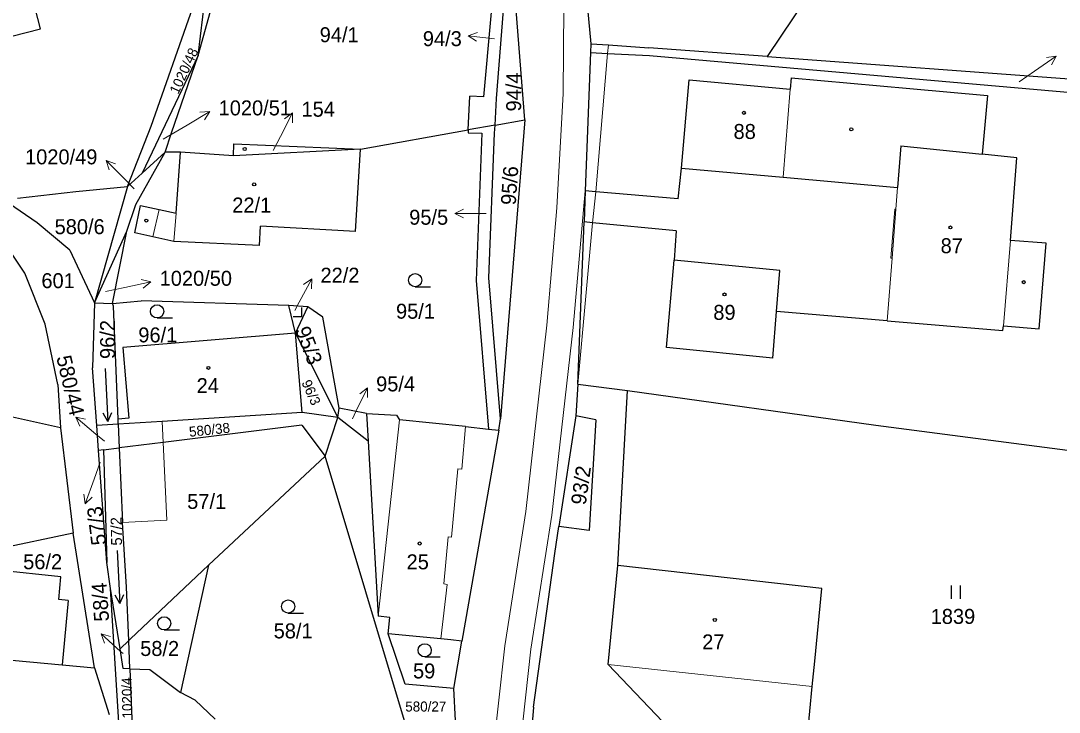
# Model space of a CAD drawing. Extents: x -601131 to -597152, y -1058536 to -1055911.
# Drawn here: x -599472.1 to -599354.1, y -1057055.1 to -1056976.5 of the extents above; entities that cross this region are included whole.
import ezdxf
from ezdxf.enums import TextEntityAlignment as Align

# ---------------------------------------------------------------- set-up
doc = ezdxf.new("R2010")
doc.units = 0
doc.header["$LTSCALE"] = 0.68
for name, color, linetype, lineweight in [('1', 7, 'Continuous', 25), ('13', 7, 'Continuous', 13), ('3', 7, 'Continuous', 25), ('4', 7, 'Continuous', 13), ('5', 7, 'Continuous', 25), ('7', 7, 'Continuous', 13)]:
    doc.layers.add(name, color=color, linetype=linetype, lineweight=lineweight)
doc.layers.add('2', color=7, linetype='Continuous')

msp = doc.modelspace()

# ---------------------------------------------------------------- linework, layer by layer
at = {"layer": '1'}
for p, q in [((-599409.1, -1056959.5), (-599407.35, -1056979.16)), ((-599469.83, -1056977.46), (-599473.08, -1056964.77)), ((-599418.06, -1056985.36), (-599416.53, -1056966.46)), ((-599414.84, -1056987.77), (-599416.53, -1056966.46)), ((-599451.94, -1056980.47), (-599450.86, -1056971.71)), ((-599381.53, -1056971.98), (-599387.3, -1056980.59)), ((-599457.28, -1056988.51), (-599452.54, -1056975.02)), ((-599451.94, -1056980.47), (-599450.36, -1056974.77)), ((-599482.74, -1056980.66), (-599469.83, -1056977.46)), ((-599407.35, -1056979.16), (-599407.36, -1056980.13)), ((-599407.35, -1056979.16), (-599405.34, -1056979.25)), ((-599405.34, -1056979.25), (-599400.73, -1056979.59)), ((-599387.3, -1056980.59), (-599400.73, -1056979.59)), ((-599451.94, -1056980.47), (-599458.28, -1056993.82)), ((-599454.95, -1056989.27), (-599451.94, -1056980.47)), ((-599407.36, -1056980.13), (-599407.96, -1056995.84)), ((-599407.36, -1056980.13), (-599405.42, -1056980.23)), ((-599405.42, -1056980.23), (-599400.68, -1056980.47)), ((-599400.68, -1056980.47), (-599338.49, -1056985.92)), ((-599387.3, -1056980.59), (-599338.23, -1056984.23)), ((-599397.05, -1056993.26), (-599396.16, -1056983.24)), ((-599396.16, -1056983.24), (-599384.69, -1056984.29)), ((-599384.57, -1056983), (-599384.69, -1056984.29)), ((-599384.57, -1056983), (-599371.09, -1056984.22)), ((-599371.09, -1056984.22), (-599362.27, -1056985.01)), ((-599421.26, -1056988.92), (-599421.08, -1056985.09)), ((-599418.21, -1056988.37), (-599418.06, -1056985.36)), ((-599362.27, -1056985.01), (-599362.87, -1056991.68)), ((-599418.21, -1056988.37), (-599414.84, -1056987.77)), ((-599414.84, -1056987.77), (-599417.59, -1057021.75)), ((-599459.98, -1056995.37), (-599457.28, -1056988.51)), ((-599455.67, -1056991.45), (-599454.95, -1056989.27)), ((-599433.51, -1056991.1), (-599421.26, -1056988.92)), ((-599421.26, -1056988.92), (-599421.28, -1056989.24)), ((-599421.28, -1056989.24), (-599419.7, -1056989.31)), ((-599418.21, -1056988.37), (-599421.26, -1056988.92)), ((-599419.7, -1056989.31), (-599420.34, -1057006.01)), ((-599418.91, -1057005.71), (-599418.26, -1056989.29)), ((-599418.26, -1056989.29), (-599418.21, -1056988.37)), ((-599447.93, -1056991.85), (-599447.87, -1056990.49)), ((-599447.87, -1056990.49), (-599433.51, -1056991.1)), ((-599459.02, -1056997.4), (-599455.67, -1056991.45)), ((-599458.28, -1056993.82), (-599455.67, -1056991.45)), ((-599453.94, -1056991.44), (-599455.67, -1056991.45)), ((-599454.45, -1056998.37), (-599453.94, -1056991.44)), ((-599447.93, -1056991.85), (-599453.94, -1056991.44)), ((-599433.51, -1056991.1), (-599447.93, -1056991.85)), ((-599434.07, -1057000.46), (-599433.51, -1056991.1)), ((-599372.12, -1056990.74), (-599372.49, -1056995.45)), ((-599372.12, -1056990.74), (-599362.87, -1056991.68)), ((-599358.94, -1056992.08), (-599362.87, -1056991.68)), ((-599359.68, -1057001.47), (-599358.94, -1056992.08)), ((-599470.21, -1056999.49), (-599478.7, -1056993.76)), ((-599459.98, -1056995.37), (-599458.28, -1056993.82)), ((-599397.4, -1056996.74), (-599397.05, -1056993.26)), ((-599397.05, -1056993.26), (-599385.47, -1056994.29)), ((-599385.47, -1056994.29), (-599372.49, -1056995.45)), ((-599472.45, -1056996.68), (-599465.82, -1056995.91)), ((-599465.82, -1056995.91), (-599459.98, -1056995.37)), ((-599459.98, -1056995.37), (-599463.72, -1057008.55)), ((-599407.96, -1056995.84), (-599408.09, -1056999.38)), ((-599406.78, -1056995.94), (-599407.96, -1056995.84)), ((-599397.4, -1056996.74), (-599406.78, -1056995.94)), ((-599460.03, -1057000.43), (-599459.02, -1056997.4)), ((-599459.12, -1057000.61), (-599458.49, -1056997.5)), ((-599458.49, -1056997.5), (-599456.38, -1056997.96)), ((-599456.38, -1056997.96), (-599454.45, -1056998.37)), ((-599466.52, -1057002.58), (-599470.21, -1056999.49)), ((-599444.97, -1057002.05), (-599444.85, -1056999.86)), ((-599434.07, -1057000.46), (-599444.85, -1056999.86)), ((-599408.79, -1057017.81), (-599408.09, -1056999.38)), ((-599407.13, -1056999.47), (-599408.09, -1056999.38)), ((-599397.65, -1057000.39), (-599407.13, -1056999.47)), ((-599463.72, -1057008.55), (-599460.03, -1057000.43)), ((-599461.67, -1057008.63), (-599460.03, -1057000.43)), ((-599457.07, -1057001.07), (-599459.12, -1057000.61)), ((-599454.69, -1057001.61), (-599457.07, -1057001.07)), ((-599397.65, -1057000.39), (-599397.85, -1057003.72)), ((-599444.97, -1057002.05), (-599454.69, -1057001.61)), ((-599355.61, -1057001.8), (-599359.68, -1057001.47)), ((-599356.39, -1057011.51), (-599355.61, -1057001.8)), ((-599471.61, -1057005.21), (-599473.53, -1057002.36)), ((-599466.52, -1057002.58), (-599463.72, -1057008.55)), ((-599398.74, -1057013.65), (-599397.85, -1057003.72)), ((-599385.87, -1057004.88), (-599397.85, -1057003.72)), ((-599469.32, -1057010.99), (-599471.61, -1057005.21)), ((-599417.59, -1057021.75), (-599418.91, -1057005.71)), ((-599386.24, -1057009.56), (-599385.87, -1057004.88)), ((-599420.34, -1057006.01), (-599418.94, -1057022.91)), ((-599463.72, -1057008.55), (-599463.92, -1057015.93)), ((-599463.72, -1057008.55), (-599461.67, -1057008.63)), ((-599461.67, -1057008.63), (-599458.42, -1057008.35)), ((-599461.55, -1057008.94), (-599461.67, -1057008.63)), ((-599461.04, -1057021.77), (-599461.55, -1057008.94)), ((-599441.62, -1057008.88), (-599458.42, -1057008.35)), ((-599439.46, -1057009), (-599441.62, -1057008.88)), ((-599440.89, -1057012), (-599441.62, -1057008.88)), ((-599440.89, -1057012), (-599439.46, -1057009)), ((-599437.78, -1057010.19), (-599439.46, -1057009)), ((-599435.93, -1057020.54), (-599437.78, -1057010.19)), ((-599386.66, -1057014.83), (-599386.24, -1057009.56)), ((-599373.69, -1057010.61), (-599386.24, -1057009.56)), ((-599467.86, -1057017.84), (-599469.32, -1057010.99)), ((-599373.69, -1057010.61), (-599360.53, -1057011.71)), ((-599360.53, -1057011.71), (-599360.46, -1057011.18)), ((-599360.46, -1057011.18), (-599356.39, -1057011.51)), ((-599440.89, -1057012), (-599460.49, -1057013.64)), ((-599440.89, -1057012), (-599436.08, -1057021.6)), ((-599440.13, -1057021), (-599440.89, -1057012)), ((-599460.49, -1057013.64), (-599459.82, -1057021.67)), ((-599386.66, -1057014.83), (-599398.74, -1057013.65)), ((-599463.44, -1057022.51), (-599463.92, -1057015.93)), ((-599467.56, -1057022.76), (-599489.04, -1057018.02)), ((-599467.86, -1057017.84), (-599467.56, -1057022.76)), ((-599408.79, -1057017.81), (-599409.03, -1057021.4)), ((-599408.79, -1057017.81), (-599403.17, -1057018.53)), ((-599404.27, -1057038.38), (-599403.17, -1057018.53)), ((-599403.17, -1057018.53), (-599374.96, -1057022.46)), ((-599440.13, -1057021), (-599456.04, -1057022.03)), ((-599436.08, -1057021.6), (-599440.13, -1057021)), ((-599436.08, -1057021.6), (-599435.93, -1057020.54)), ((-599432.8, -1057021.13), (-599435.93, -1057020.54)), ((-599432.8, -1057021.13), (-599432.62, -1057024.26)), ((-599432.8, -1057021.13), (-599429.39, -1057021.33)), ((-599461.01, -1057022.35), (-599463.44, -1057022.51)), ((-599459.82, -1057021.67), (-599461.04, -1057021.77)), ((-599461.01, -1057022.35), (-599461.04, -1057021.77)), ((-599456.04, -1057022.03), (-599461.01, -1057022.35)), ((-599461.01, -1057022.35), (-599460.9, -1057025.03)), ((-599437.5, -1057025.97), (-599436.08, -1057021.6)), ((-599432.62, -1057024.26), (-599436.08, -1057021.6)), ((-599429.39, -1057021.33), (-599429.05, -1057021.83)), ((-599421.58, -1057022.62), (-599429.05, -1057021.83)), ((-599417.77, -1057023.04), (-599417.59, -1057021.75)), ((-599409.03, -1057021.4), (-599410.96, -1057033.98)), ((-599406.78, -1057021.84), (-599409.03, -1057021.4)), ((-599406.78, -1057021.84), (-599407.53, -1057034.4)), ((-599467.56, -1057022.76), (-599466.14, -1057034.71)), ((-599463.24, -1057025.32), (-599463.44, -1057022.51)), ((-599440.17, -1057022.45), (-599455.92, -1057024.41)), ((-599440.17, -1057022.45), (-599437.5, -1057025.97)), ((-599417.77, -1057023.04), (-599421.97, -1057047)), ((-599421.58, -1057022.62), (-599418.94, -1057022.91)), ((-599418.94, -1057022.91), (-599417.77, -1057023.04)), ((-599374.96, -1057022.46), (-599345.57, -1057026.31)), ((-599455.92, -1057024.41), (-599460.9, -1057025.03)), ((-599432.62, -1057024.26), (-599431.47, -1057044.16)), ((-599462.69, -1057025.25), (-599463.24, -1057025.32)), ((-599462.31, -1057038.06), (-599463.24, -1057025.32)), ((-599462.69, -1057025.25), (-599460.9, -1057025.03)), ((-599462.69, -1057025.25), (-599462.31, -1057038.06)), ((-599460.9, -1057025.03), (-599460.52, -1057033.5)), ((-599450.76, -1057038.35), (-599437.5, -1057025.97)), ((-599428.27, -1057056.8), (-599437.5, -1057025.97)), ((-599460.07, -1057040.85), (-599460.52, -1057033.5)), ((-599411.41, -1057037.02), (-599410.96, -1057033.98)), ((-599407.53, -1057034.4), (-599410.96, -1057033.98)), ((-599466.14, -1057034.71), (-599476.85, -1057036.98)), ((-599463.71, -1057050), (-599466.14, -1057034.71)), ((-599413.85, -1057054.49), (-599411.41, -1057037.02)), ((-599467.53, -1057039.67), (-599480.14, -1057038.37)), ((-599461.88, -1057041.02), (-599462.31, -1057038.06)), ((-599459.62, -1057046.73), (-599450.76, -1057038.35)), ((-599450.76, -1057038.35), (-599453.93, -1057052.81)), ((-599405.37, -1057049.65), (-599404.27, -1057038.38)), ((-599381.08, -1057041), (-599404.27, -1057038.38)), ((-599467.75, -1057042.26), (-599467.53, -1057039.67)), ((-599460.81, -1057047.86), (-599461.88, -1057041.02)), ((-599460.91, -1057056.82), (-599461.88, -1057041.02)), ((-599459.82, -1057046.92), (-599460.07, -1057040.85)), ((-599381.87, -1057049.25), (-599381.08, -1057041)), ((-599466.69, -1057042.35), (-599467.75, -1057042.26)), ((-599466.69, -1057042.35), (-599467.37, -1057049.67)), ((-599430.18, -1057044.28), (-599431.47, -1057044.16)), ((-599430.36, -1057046.16), (-599430.18, -1057044.28)), ((-599459.82, -1057046.92), (-599460.81, -1057047.86)), ((-599459.82, -1057046.92), (-599459.62, -1057046.73)), ((-599459.69, -1057050.12), (-599459.82, -1057046.92)), ((-599428.44, -1057051.87), (-599430.36, -1057046.16)), ((-599424.38, -1057046.72), (-599430.36, -1057046.16)), ((-599423.25, -1057046.85), (-599424.38, -1057046.72)), ((-599421.97, -1057047), (-599423.25, -1057046.85)), ((-599422.91, -1057052.37), (-599421.97, -1057047)), ((-599488.12, -1057047.79), (-599467.37, -1057049.67)), ((-599460.46, -1057050.1), (-599460.81, -1057047.86)), ((-599382.18, -1057052.14), (-599381.87, -1057049.25)), ((-599467.37, -1057049.67), (-599463.71, -1057050)), ((-599463.71, -1057050), (-599462.05, -1057055.3)), ((-599459.69, -1057050.12), (-599460.46, -1057050.1)), ((-599459.69, -1057050.12), (-599459.42, -1057056.74)), ((-599459.69, -1057050.12), (-599457.43, -1057050.19)), ((-599457.43, -1057050.19), (-599453.93, -1057052.81)), ((-599393.36, -1057062.2), (-599405.37, -1057049.65)), ((-599452.28, -1057053.7), (-599453.93, -1057052.81)), ((-599422.91, -1057052.37), (-599428.44, -1057051.87)), ((-599422.72, -1057056), (-599422.91, -1057052.37)), ((-599383.28, -1057063.21), (-599382.18, -1057052.14)), ((-599450.01, -1057055.83), (-599452.28, -1057053.7)), ((-599413.85, -1057054.49), (-599415.07, -1057069.81))]:
    msp.add_line(p, q, dxfattribs=at)
msp.add_lwpolyline([(-599417.86, -1056966.74), (-599419.51, -1056985.16), (-599421.08, -1056985.09)], dxfattribs=at)
at = {"layer": '13'}
for points in [[(-599416.28, -1057067.22), (-599414.13, -1057047.91), (-599411.76, -1057032.68), (-599409.33, -1057011.38), (-599407.96, -1056995.84), (-599407.36, -1056980.13), (-599407.35, -1056979.16), (-599409.1, -1056959.5), (-599412.79, -1056937.66), (-599414.89, -1056928.62), (-599418.98, -1056914.8), (-599422.34, -1056903.17), (-599429.56, -1056878.4), (-599431.63, -1056868.93), (-599432.99, -1056860.71)], [(-599435.97, -1056861.08), (-599434.58, -1056869.5), (-599432.48, -1056879.1), (-599425.21, -1056904.03), (-599421.86, -1056915.62), (-599416.39, -1056935.17), (-599414.31, -1056943.54), (-599413.29, -1056949.55), (-599410.84, -1056967.85), (-599410.4, -1056975), (-599410.48, -1056984.78), (-599411.21, -1056997.76), (-599412.32, -1057011.09), (-599414.73, -1057032.27), (-599417.11, -1057047.5), (-599419.27, -1057067.05)]]:
    msp.add_lwpolyline(points, dxfattribs=at)
at = {"layer": '3'}
for p, q in [((-599427.293, -1057006.74), (-599425.543, -1057006.74)), ((-599456.603, -1057010.28), (-599454.853, -1057010.28)), ((-599462.191, -1057022.023), (-599462.743, -1057021.074)), ((-599366.361, -1057042.18), (-599366.361, -1057040.68)), ((-599365.36, -1057042.18), (-599365.36, -1057040.68)), ((-599460.821, -1057042.693), (-599461.373, -1057041.744)), ((-599441.703, -1057043.8), (-599439.953, -1057043.8)), ((-599455.803, -1057045.71), (-599454.053, -1057045.71)), ((-599426.203, -1057048.77), (-599424.453, -1057048.77))]:
    msp.add_line(p, q, dxfattribs=at)
for points in [[(-599441.151, -1057010.11), (-599440.15, -1057010.11), (-599440.15, -1057009.11)], [(-599462.505, -1057016.032), (-599462.191, -1057022.023), (-599461.741, -1057021.021)], [(-599461.135, -1057036.702), (-599460.821, -1057042.693), (-599460.371, -1057041.691)]]:
    msp.add_lwpolyline(points, dxfattribs=at)
for centre in [(-599427.2929, -1057005.9898), (-599456.6029, -1057009.5298), (-599441.7029, -1057043.0498), (-599455.8029, -1057044.9598), (-599426.2029, -1057048.0198)]:
    msp.add_circle(centre, 0.75, dxfattribs=at)
at = {"layer": '4'}
for p, q in [((-599405.42, -1056980.23), (-599405.34, -1056979.25)), ((-599405.42, -1056980.23), (-599406.78, -1056995.94)), ((-599384.69, -1056984.29), (-599385.47, -1056994.29)), ((-599406.78, -1056995.94), (-599407.13, -1056999.47)), ((-599372.67, -1056997.94), (-599372.49, -1056995.45)), ((-599457.07, -1057001.07), (-599456.38, -1056997.96)), ((-599454.69, -1057001.61), (-599454.45, -1056998.37)), ((-599373.25, -1057003.49), (-599372.8, -1056997.92)), ((-599373.11, -1057003.49), (-599372.67, -1056997.94)), ((-599372.8, -1056997.92), (-599372.67, -1056997.94)), ((-599407.13, -1056999.47), (-599408.79, -1057017.81)), ((-599360.46, -1057011.18), (-599359.68, -1057001.47)), ((-599373.69, -1057010.61), (-599373.11, -1057003.49)), ((-599373.11, -1057003.49), (-599373.25, -1057003.49)), ((-599455.92, -1057024.41), (-599456.04, -1057022.03)), ((-599429.05, -1057021.83), (-599431.47, -1057044.16)), ((-599422, -1057027.44), (-599421.58, -1057022.62)), ((-599455.48, -1057033.23), (-599455.92, -1057024.41)), ((-599423.15, -1057035.16), (-599422.45, -1057027.4)), ((-599422, -1057027.44), (-599422.45, -1057027.4)), ((-599460.52, -1057033.5), (-599455.48, -1057033.23)), ((-599424.03, -1057040.49), (-599423.52, -1057035.12)), ((-599423.15, -1057035.16), (-599423.52, -1057035.12)), ((-599424.38, -1057046.72), (-599423.66, -1057040.53)), ((-599423.66, -1057040.53), (-599424.03, -1057040.49)), ((-599405.37, -1057049.65), (-599382.18, -1057052.14))]:
    msp.add_line(p, q, dxfattribs=at)
at = {"layer": '5'}
for centre in [(-599389.9468, -1056986.9892), (-599377.7468, -1056988.8692), (-599446.6468, -1056991.0892), (-599445.5768, -1056995.1092), (-599457.8268, -1056999.2192), (-599366.4868, -1056999.9992), (-599358.1568, -1057006.2192), (-599392.1468, -1057007.6092), (-599450.7668, -1057015.9492), (-599426.7668, -1057035.8892), (-599393.2468, -1057044.5792)]:
    msp.add_circle(centre, 0.175, dxfattribs=at)
at = {"layer": '7'}
for p, q in [((-599421.249, -1056978.234), (-599420.316, -1056978.853)), ((-599354.482, -1056980.539), (-599355.589, -1056980.703)), ((-599450.618, -1056986.824), (-599451.734, -1056986.911)), ((-599441.218, -1056986.996), (-599442.118, -1056987.661)), ((-599462.382, -1056992.408), (-599462.028, -1056993.47)), ((-599422.791, -1056998.41), (-599421.79, -1056998.911)), ((-599439.041, -1057005.85), (-599439.953, -1057006.499)), ((-599457.315, -1057006.186), (-599458.398, -1057005.904)), ((-599432.694, -1057018.203), (-599433.584, -1057018.883)), ((-599465.839, -1057021.531), (-599465.394, -1057022.558)), ((-599464.786, -1057031.4), (-599463.973, -1057030.63)), ((-599462.97, -1057046.152), (-599462.561, -1057047.194))]:
    msp.add_line(p, q, dxfattribs=at)
for points in [[(-599418.27, -1056978.6), (-599421.249, -1056978.234), (-599420.194, -1056977.859)], [(-599358.68, -1056983.47), (-599356.94, -1056982.26), (-599354.482, -1056980.539), (-599355.015, -1056981.523)], [(-599455.92, -1056989.98), (-599453.19, -1056988.37), (-599450.618, -1056986.824), (-599451.218, -1056987.769)], [(-599443.41, -1056991.28), (-599442.58, -1056989.67), (-599441.218, -1056986.996), (-599441.226, -1056988.116)], [(-599459.2, -1056995.6), (-599460.26, -1056994.53), (-599462.382, -1056992.408), (-599461.32, -1056992.762)], [(-599419.21, -1056998.41), (-599419.79, -1056998.41), (-599422.791, -1056998.41), (-599421.79, -1056997.909)], [(-599440.95, -1057009.44), (-599440.45, -1057008.5), (-599439.041, -1057005.85), (-599439.069, -1057006.97)], [(-599462.45, -1057007.26), (-599460.25, -1057006.81), (-599457.315, -1057006.186), (-599458.19, -1057006.884)], [(-599434.41, -1057021.73), (-599434.01, -1057020.9), (-599432.694, -1057018.203), (-599432.683, -1057019.322)], [(-599462.58, -1057024.26), (-599463.54, -1057023.46), (-599465.839, -1057021.531), (-599464.75, -1057021.791)], [(-599463.07, -1057026.67), (-599463.76, -1057028.58), (-599464.786, -1057031.4), (-599464.914, -1057030.288)], [(-599460.47, -1057048.4), (-599460.74, -1057048.16), (-599462.97, -1057046.152), (-599461.891, -1057046.45)]]:
    msp.add_lwpolyline(points, dxfattribs=at)

# ---------------------------------------------------------------- texts
at = {"layer": '2'}
for s, height, p in [('94/1', 1.7, (-599438.13, -1056978.965)), ('1020/51', 1.7, (-599449.61, -1056987.275)), ('154', 1.7, (-599440.2, -1056987.425)), ('88', 1.7, (-599391.12, -1056989.955)), ('22/1', 1.7, (-599448.06, -1056998.304)), ('580/6', 1.7, (-599468.24, -1057000.765)), ('87', 1.7, (-599367.6, -1057002.925)), ('22/2', 1.7, (-599438.04, -1057006.275)), ('601', 1.7, (-599469.74, -1057006.895)), ('1020/50', 1.7, (-599456.31, -1057006.625)), ('95/1', 1.7, (-599429.46, -1057010.365)), ('89', 1.7, (-599393.42, -1057010.495)), ('96/1', 1.7, (-599458.73, -1057013.054)), ('24', 1.7, (-599452.11, -1057018.814)), ('95/4', 1.7, (-599431.72, -1057018.615)), ('57/1', 1.7, (-599453.18, -1057031.965)), ('56/2', 1.7, (-599471.81, -1057038.814)), ('25', 1.7, (-599428.26, -1057038.824)), ('58/1', 1.7, (-599443.36, -1057046.665)), ('58/2', 1.7, (-599458.52, -1057048.665)), ('27', 1.7, (-599394.68, -1057047.915)), ('59', 1.7, (-599427.53, -1057051.215)), ('580/27', 1.14, (-599428.41, -1057054.975))]:
    msp.add_text(s, height=height, dxfattribs=at).set_placement(p)
for s, p in [('94/3', (-599421.989, -1056979.412)), ('1020/49', (-599463.38, -1056992.834)), ('95/5', (-599423.539, -1056999.692))]:
    msp.add_text(s, height=1.7, dxfattribs=at).set_placement(p, align=Align.RIGHT)
for s, height, rotation, p in [('1020/48', 1.14, 65, (-599453.044, -1056982.4579)), ('94/4', 1.7, 90, (-599415.245, -1056984.619)), ('95/6', 1.7, 86, (-599415.713, -1056995.2993)), ('580/38', 1.14, 6, (-599450.5896, -1057023.5398))]:
    msp.add_text(s, height=height, rotation=rotation, dxfattribs=at).set_placement(p, align=Align.CENTER)
for s, height, rotation, p in [('96/2', 1.7, 90, (-599461.375, -1057014.94)), ('95/3', 1.7, 291, (-599440.946, -1057011.632)), ('96/3', 1.14, 294, (-599440.22, -1057017.615)), ('93/2', 1.7, 82, (-599407.919, -1057031.589)), ('57/2', 1.24, 91, (-599460.58, -1057036.114)), ('1020/4', 1.14, 91, (-599459.405, -1057055.755))]:
    msp.add_text(s, height=height, rotation=rotation, dxfattribs=at).set_placement(p)
for s, rotation, p in [('580/44', 283, (-599466.4883, -1057021.5206)), ('57/3', 97, (-599462.8957, -1057031.5912)), ('58/4', 94, (-599462.35, -1057040.2896))]:
    msp.add_text(s, height=1.7, rotation=rotation, dxfattribs=at).set_placement(p, align=Align.RIGHT)
msp.add_text('1839', height=1.7, dxfattribs=at).set_placement((-599366.2, -1057045.022), align=Align.CENTER)

doc.saveas('drawing.dxf')
